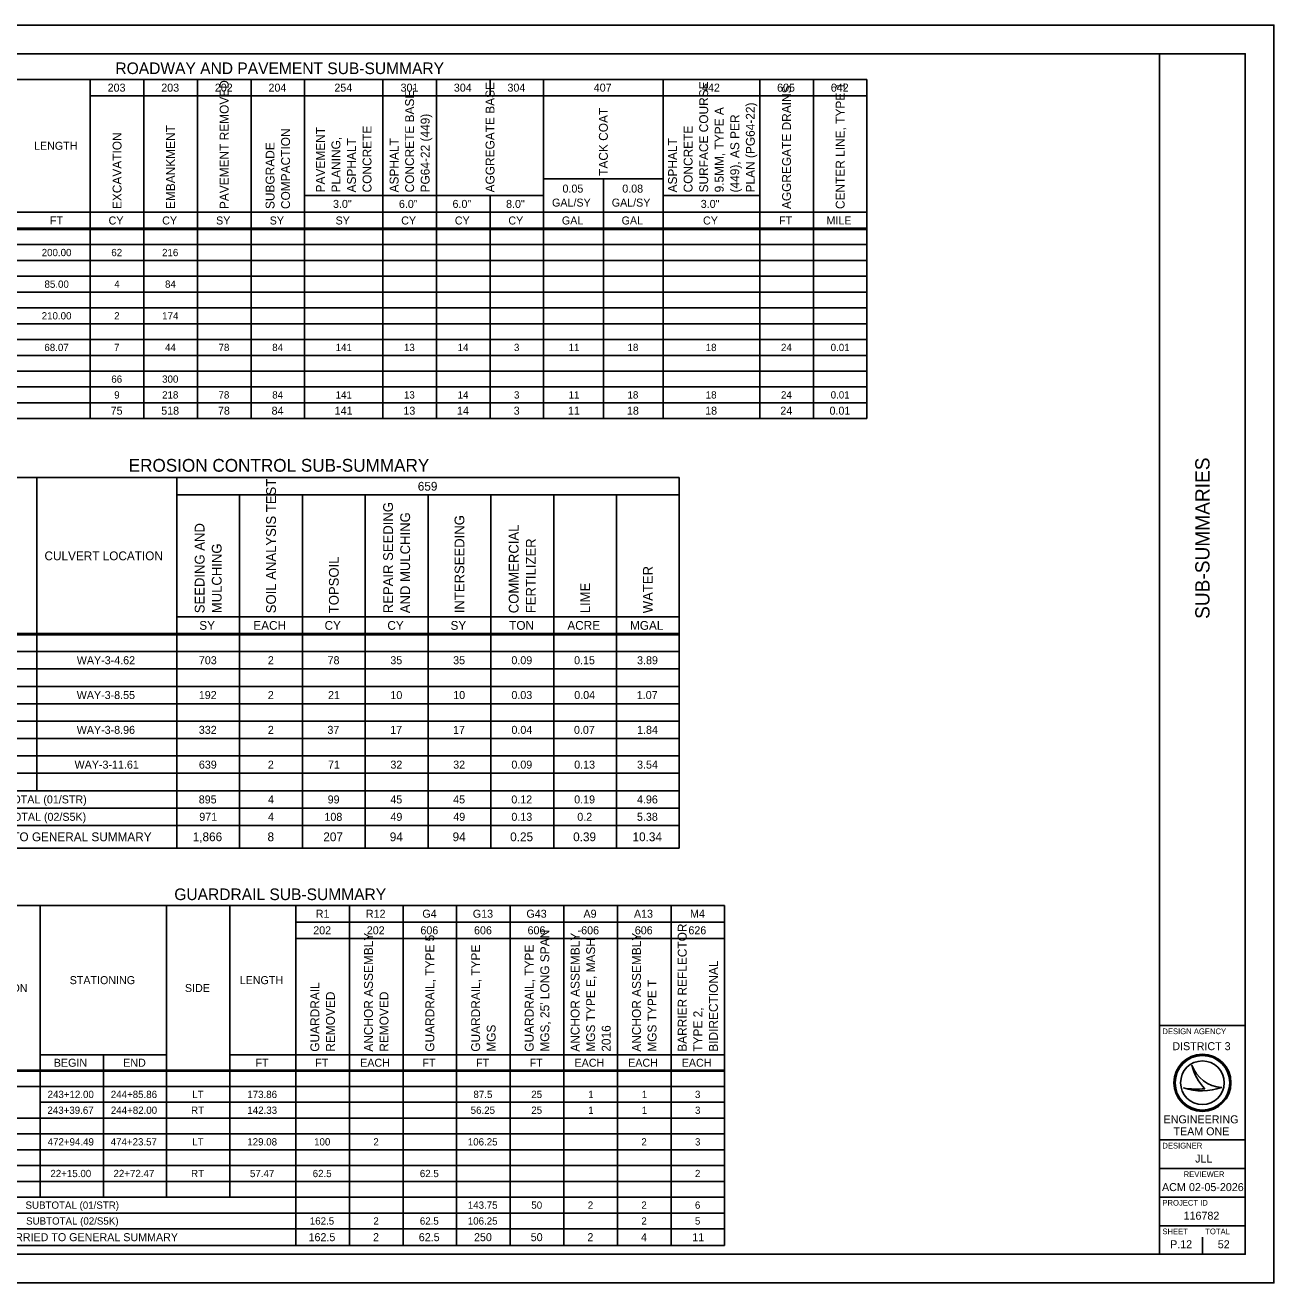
# Model space of a CAD drawing. Extents: x 0 to 34, y 0 to 22.
# Drawn here: x 12.15 to 34, y 0 to 22 of the extents above; entities that cross this region are included whole.
import ezdxf

# ---------------------------------------------------------------- set-up
doc = ezdxf.new("R2010")
doc.units = 0
for name, color, linetype in [('SH_Border', 7, 'Continuous'), ('SH_Cut_Line', 7, 'Continuous'), ('SH_Data', 7, 'Continuous'), ('SH_Text', 7, 'Continuous')]:
    doc.layers.add(name, color=color, linetype=linetype)

msp = doc.modelspace()

# ---------------------------------------------------------------- linework, layer by layer
at = {"layer": 'SH_Border'}
for p, q in [((32, 0.5), (32, 21.5)), ((32, 4.5), (33.5, 4.5)), ((32, 2.5), (33.5, 2.5)), ((32, 2), (33.5, 2)), ((32, 1.5), (33.5, 1.5)), ((32, 1), (33.5, 1))]:
    msp.add_line(p, q, dxfattribs=at)
msp.add_lwpolyline([(1.5, 21.5), (33.5, 21.5), (33.5, 0.5), (1.5, 0.5)], close=True, dxfattribs=at)
at = {"layer": 'SH_Cut_Line'}
msp.add_lwpolyline([(0, 0), (34, 0), (34, 22), (0, 22)], close=True, dxfattribs=at)
at = {"layer": 'SH_Data'}
for p, q in [((32.567, 3.81), (32.567, 3.81)), ((32.417, 3.41), (32.417, 3.41)), ((32.75, 3.5), (32.75, 3.5)), ((33.087, 3.419), (33.087, 3.419)), ((32.375, 0.675), (32.375, 0.675)), ((32.75, 0.5), (32.75, 0.8))]:
    msp.add_line(p, q, dxfattribs=at)
for radius in [0.5, 0.477, 0.477, 0.382]:
    msp.add_circle((32.75, 3.5), radius, dxfattribs=at)
for centre, radius, start, end in [((33.116, 3.998), 0.58, 198.9257, 198.9319), ((33.347, 3.97), 0.796, 191.6379, 191.6421), ((33.116, 3.998), 0.58, 198.9319, 267.1657), ((33.347, 3.97), 0.796, 191.6421, 226.0947), ((32.739, 4.37), 1.013, 251.4576, 290.0832), ((32.648, 4.654), 1.266, 259.4964, 259.4995), ((32.739, 4.37), 1.013, 251.4527, 251.4576), ((32.648, 4.654), 1.266, 259.4995, 276.6672)]:
    msp.add_arc(centre, radius, start, end, dxfattribs=at)
at = {"layer": 'SH_Text'}
for p, q in [((6.619, 21.052), (26.881, 21.052)), ((13.291, 21.052), (13.291, 18.447)), ((14.229, 21.052), (14.229, 18.447)), ((15.167, 21.052), (15.167, 18.447)), ((16.104, 21.052), (16.104, 18.447)), ((17.042, 21.052), (17.042, 18.447)), ((18.41, 21.052), (18.41, 18.447)), ((19.348, 21.052), (19.348, 18.447)), ((20.286, 21.052), (20.286, 20.762)), ((21.224, 21.052), (21.224, 18.447)), ((23.314, 21.052), (23.314, 18.447)), ((25.005, 21.052), (25.005, 18.447)), ((25.943, 21.052), (25.943, 18.447)), ((26.881, 21.052), (26.881, 18.428)), ((13.291, 20.762), (26.881, 20.762)), ((21.224, 19.309), (23.314, 19.309)), ((22.269, 19.309), (22.269, 18.447)), ((17.042, 19.019), (21.224, 19.019)), ((20.286, 19.019), (20.286, 18.447)), ((23.314, 19.019), (25.005, 19.019)), ((9.924, 18.728), (26.881, 18.728)), ((6.619, 18.447), (26.881, 18.447)), ((6.619, 18.428), (26.881, 18.428)), ((13.291, 18.428), (13.291, 15.117)), ((14.229, 18.428), (14.229, 15.117)), ((15.167, 18.428), (15.167, 15.117)), ((16.104, 18.428), (16.104, 15.117)), ((17.042, 18.428), (17.042, 15.117)), ((18.41, 18.428), (18.41, 15.117)), ((19.348, 18.428), (19.348, 15.117)), ((20.286, 18.428), (20.286, 15.117)), ((21.224, 18.428), (21.224, 15.117)), ((22.269, 18.428), (22.269, 15.117)), ((23.314, 18.428), (23.314, 15.117)), ((25.005, 18.428), (25.005, 15.117)), ((25.943, 18.428), (25.943, 15.117)), ((26.881, 18.447), (26.881, 15.117)), ((6.619, 18.161), (26.881, 18.161)), ((6.619, 17.884), (26.881, 17.884)), ((6.619, 17.607), (26.881, 17.607)), ((6.619, 17.331), (26.881, 17.331)), ((6.619, 17.054), (26.881, 17.054)), ((6.619, 16.777), (26.881, 16.777)), ((6.619, 16.501), (26.881, 16.501)), ((6.619, 16.224), (26.881, 16.224)), ((6.619, 15.947), (26.881, 15.947)), ((6.619, 15.671), (26.881, 15.671)), ((6.619, 15.394), (26.881, 15.394)), ((6.619, 15.117), (26.881, 15.117)), ((9.902, 14.087), (23.598, 14.087)), ((12.354, 14.087), (12.354, 11.358)), ((14.806, 14.087), (14.806, 11.358)), ((23.598, 14.087), (23.598, 11.337)), ((14.806, 13.782), (23.598, 13.782)), ((15.905, 13.782), (15.905, 11.358)), ((17.004, 13.782), (17.004, 11.358)), ((18.103, 13.782), (18.103, 11.358)), ((19.202, 13.782), (19.202, 11.358)), ((20.301, 13.782), (20.301, 11.358)), ((21.4, 13.782), (21.4, 11.358)), ((22.499, 13.782), (22.499, 11.358)), ((14.806, 11.652), (23.598, 11.652)), ((9.902, 11.358), (23.598, 11.358)), ((9.902, 11.337), (23.598, 11.337)), ((12.354, 11.337), (12.354, 8.608)), ((14.806, 11.337), (14.806, 7.604)), ((15.905, 11.337), (15.905, 7.604)), ((17.004, 11.337), (17.004, 7.604)), ((18.103, 11.337), (18.103, 7.604)), ((19.202, 11.337), (19.202, 7.604)), ((20.301, 11.337), (20.301, 7.604)), ((21.4, 11.337), (21.4, 7.604)), ((22.499, 11.337), (22.499, 7.604)), ((23.598, 11.358), (23.598, 7.604)), ((9.902, 11.043), (23.598, 11.043)), ((9.902, 10.739), (23.598, 10.739)), ((9.902, 10.434), (23.598, 10.434)), ((9.902, 10.13), (23.598, 10.13)), ((9.902, 9.826), (23.598, 9.826)), ((9.902, 9.521), (23.598, 9.521)), ((9.902, 9.217), (23.598, 9.217)), ((9.902, 8.913), (23.598, 8.913)), ((9.902, 8.608), (23.598, 8.608)), ((9.902, 8.304), (23.598, 8.304)), ((9.902, 8), (23.598, 8)), ((9.902, 7.604), (23.598, 7.604)), ((9.109, 6.603), (24.391, 6.603)), ((12.415, 6.603), (12.415, 3.721)), ((14.628, 6.603), (14.628, 3.721)), ((15.735, 6.603), (15.735, 3.721)), ((16.888, 6.603), (16.888, 3.721)), ((17.826, 6.603), (17.826, 3.721)), ((18.764, 6.603), (18.764, 3.721)), ((19.702, 6.603), (19.702, 3.721)), ((20.639, 6.603), (20.639, 3.721)), ((21.577, 6.603), (21.577, 3.721)), ((22.515, 6.603), (22.515, 3.721)), ((23.453, 6.603), (23.453, 3.721)), ((24.391, 6.603), (24.391, 3.702)), ((16.888, 6.312), (24.391, 6.312)), ((16.888, 6.022), (24.391, 6.022)), ((12.415, 3.988), (14.628, 3.988)), ((13.522, 3.988), (13.522, 3.721)), ((15.735, 3.988), (24.391, 3.988)), ((9.109, 3.721), (24.391, 3.721)), ((9.109, 3.702), (24.391, 3.702)), ((12.415, 3.702), (12.415, 1.498)), ((13.522, 3.702), (13.522, 1.498)), ((14.628, 3.702), (14.628, 1.498)), ((15.735, 3.702), (15.735, 1.498)), ((16.888, 3.702), (16.888, 0.654)), ((17.826, 3.702), (17.826, 0.654)), ((18.764, 3.702), (18.764, 0.654)), ((19.702, 3.702), (19.702, 0.654)), ((20.639, 3.702), (20.639, 0.654)), ((21.577, 3.702), (21.577, 0.654)), ((22.515, 3.702), (22.515, 0.654)), ((23.453, 3.702), (23.453, 0.654)), ((24.391, 3.721), (24.391, 0.654)), ((9.109, 3.435), (24.391, 3.435)), ((12.415, 3.158), (24.391, 3.158)), ((9.109, 2.881), (24.391, 2.881)), ((9.109, 2.605), (24.391, 2.605)), ((9.109, 2.328), (24.391, 2.328)), ((9.109, 2.051), (24.391, 2.051)), ((9.109, 1.775), (24.391, 1.775)), ((9.109, 1.498), (24.391, 1.498)), ((9.109, 1.221), (24.391, 1.221)), ((9.109, 0.945), (24.391, 0.945)), ((9.109, 0.654), (24.391, 0.654))]:
    msp.add_line(p, q, dxfattribs=at)

# ---------------------------------------------------------------- texts
at = {"layer": 'SH_Data'}
msp.add_text('SUB-SUMMARIES', height=0.25, rotation=90, dxfattribs=at).set_placement((32.875, 11.614))
for s, height, p in [('DESIGN AGENCY', 0.1, (32.05, 4.35)), ('DISTRICT 3', 0.14, (32.224, 4.07)), ('ENGINEERING', 0.14, (32.071, 2.79)), ('TEAM ONE', 0.14, (32.244, 2.58)), ('DESIGNER', 0.1, (32.05, 2.35)), ('JLL', 0.14, (32.623, 2.105)), ('REVIEWER', 0.1, (32.422, 1.85)), ('ACM', 0.14, (32.043, 1.605)), ('02-05-2026', 0.14, (32.515, 1.605)), ('PROJECT ID', 0.1, (32.05, 1.35)), ('116782', 0.14, (32.421, 1.105)), ('SHEET', 0.1, (32.05, 0.85)), ('TOTAL', 0.1, (32.8, 0.85)), ('P.12', 0.14, (32.185, 0.605)), ('52', 0.14, (33.019, 0.605))]:
    msp.add_text(s, height=height, dxfattribs=at).set_placement(p)
at = {"layer": 'SH_Text'}
for s, height, p in [('ROADWAY AND PAVEMENT SUB-SUMMARY', 0.20364, (13.732, 21.144)), ('203', 0.14, (13.596, 20.837)), ('203', 0.14, (14.534, 20.837)), ('202', 0.14, (15.471, 20.837)), ('204', 0.14, (16.41, 20.837)), ('254', 0.14, (17.563, 20.837)), ('301', 0.14, (18.721, 20.837)), ('304', 0.14, (19.653, 20.837)), ('304', 0.14, (20.591, 20.837)), ('407', 0.14, (22.101, 20.837)), ('442', 0.14, (23.995, 20.837)), ('605', 0.14, (25.309, 20.837)), ('642', 0.14, (26.248, 20.837)), ('LENGTH', 0.14, (12.308, 19.82)), ('0.05 ', 0.14, (21.554, 19.071)), ('0.08 ', 0.14, (22.6, 19.071)), ('3.0"', 0.14, (17.539, 18.803)), ('6.0"', 0.14, (18.692, 18.803)), ('6.0"', 0.14, (19.63, 18.803)), ('8.0"', 0.14, (20.567, 18.803)), ('GAL/SY', 0.14, (21.371, 18.826)), ('GAL/SY', 0.14, (22.416, 18.826)), ('3.0"', 0.14, (23.973, 18.803)), ('FT', 0.14, (12.585, 18.513)), ('CY', 0.14, (13.612, 18.513)), ('CY', 0.14, (14.55, 18.513)), ('SY', 0.14, (15.493, 18.513)), ('SY', 0.14, (16.431, 18.513)), ('SY', 0.14, (17.584, 18.513)), ('CY', 0.14, (18.732, 18.513)), ('CY', 0.14, (19.67, 18.513)), ('CY', 0.14, (20.607, 18.513)), ('GAL', 0.14, (21.543, 18.513)), ('GAL', 0.14, (22.588, 18.513)), ('CY', 0.14, (24.013, 18.513)), ('FT', 0.14, (25.345, 18.513)), ('MILE', 0.14, (26.173, 18.513)), ('200.00', 0.1273, (12.442, 17.959)), ('62', 0.1273, (13.66, 17.959)), ('216', 0.1273, (14.548, 17.959)), ('85.00', 0.1273, (12.491, 17.406)), ('4', 0.127, (13.712, 17.406)), ('84', 0.1273, (14.6, 17.406)), ('210.00', 0.1273, (12.442, 16.852)), ('2', 0.127, (13.71, 16.852)), ('174', 0.1273, (14.55, 16.852)), ('68.07', 0.1273, (12.489, 16.299)), ('7', 0.127, (13.707, 16.299)), ('44', 0.1273, (14.6, 16.299)), ('78', 0.1273, (15.536, 16.299)), ('84', 0.1273, (16.475, 16.299)), ('141', 0.1273, (17.585, 16.299)), ('13', 0.1273, (18.78, 16.299)), ('14', 0.1273, (19.719, 16.299)), ('3', 0.127, (20.705, 16.299)), ('11', 0.1273, (21.661, 16.299)), ('18', 0.1273, (22.692, 16.299)), ('18', 0.1273, (24.06, 16.299)), ('24', 0.1273, (25.377, 16.299)), ('0.01', 0.1273, (26.246, 16.299)), ('66', 0.1273, (13.66, 15.745)), ('300', 0.1273, (14.549, 15.745)), ('9', 0.127, (13.711, 15.469)), ('218', 0.1273, (14.549, 15.469)), ('78', 0.1273, (15.536, 15.469)), ('84', 0.1273, (16.475, 15.469)), ('141', 0.1273, (17.585, 15.469)), ('13', 0.1273, (18.78, 15.469)), ('14', 0.1273, (19.719, 15.469)), ('3', 0.127, (20.705, 15.469)), ('11', 0.1273, (21.661, 15.469)), ('18', 0.1273, (22.692, 15.469)), ('18', 0.1273, (24.06, 15.469)), ('24', 0.1273, (25.377, 15.469)), ('0.01', 0.1273, (26.246, 15.469)), ('75', 0.14, (13.649, 15.186)), ('518', 0.14, (14.533, 15.186)), ('78', 0.14, (15.526, 15.186)), ('84', 0.14, (16.464, 15.186)), ('141', 0.14, (17.568, 15.186)), ('13', 0.14, (18.77, 15.186)), ('14', 0.14, (19.708, 15.186)), ('3', 0.14, (20.7, 15.186)), ('11', 0.14, (21.649, 15.186)), ('18', 0.14, (22.682, 15.186)), ('18', 0.14, (24.05, 15.186)), ('24', 0.14, (25.365, 15.186)), ('0.01', 0.14, (26.226, 15.186)), ('EROSION CONTROL SUB-SUMMARY', 0.224, (13.964, 14.188)), ('659', 0.154, (19.022, 13.857)), ('CULVERT LOCATION', 0.154, (12.491, 12.64)), ('SY', 0.154, (15.199, 11.423)), ('EACH', 0.154, (16.145, 11.423)), ('CY', 0.154, (17.391, 11.423)), ('CY', 0.154, (18.49, 11.423)), ('SY', 0.154, (19.595, 11.423)), ('TON', 0.154, (20.621, 11.423)), ('ACRE', 0.154, (21.639, 11.423)), ('MGAL', 0.154, (22.735, 11.423)), ('WAY-3-4.62', 0.14, (13.056, 10.821)), ('703', 0.14, (15.192, 10.821)), ('2', 0.14, (16.399, 10.821)), ('78', 0.14, (17.444, 10.821)), ('35', 0.14, (18.542, 10.821)), ('35', 0.14, (19.641, 10.821)), ('0.09', 0.14, (20.66, 10.821)), ('0.15', 0.14, (21.757, 10.821)), ('3.89', 0.14, (22.859, 10.821)), ('WAY-3-8.55', 0.14, (13.055, 10.212)), ('192', 0.14, (15.191, 10.212)), ('2', 0.14, (16.399, 10.212)), ('21', 0.14, (17.452, 10.212)), ('10', 0.14, (18.543, 10.212)), ('10', 0.14, (19.642, 10.212)), ('0.03', 0.14, (20.66, 10.212)), ('0.04', 0.14, (21.76, 10.212)), ('1.07', 0.14, (22.854, 10.212)), ('WAY-3-8.96', 0.14, (13.055, 9.603)), ('332', 0.14, (15.191, 9.603)), ('2', 0.14, (16.399, 9.603)), ('37', 0.14, (17.441, 9.603)), ('17', 0.14, (18.54, 9.603)), ('17', 0.14, (19.639, 9.603)), ('0.04', 0.14, (20.661, 9.603)), ('0.07', 0.14, (21.755, 9.603)), ('1.84', 0.14, (22.859, 9.603)), ('WAY-3-11.61', 0.14, (13.017, 8.995)), ('639', 0.14, (15.192, 8.995)), ('2', 0.14, (16.399, 8.995)), ('71', 0.14, (17.452, 8.995)), ('32', 0.14, (18.543, 8.995)), ('32', 0.14, (19.642, 8.995)), ('0.09', 0.14, (20.66, 8.995)), ('0.13', 0.14, (21.759, 8.995)), ('3.54', 0.14, (22.859, 8.995)), ('SUBTOTAL (01/STR)', 0.14, (11.43, 8.386)), ('895', 0.14, (15.19, 8.386)), ('4', 0.14, (16.401, 8.386)), ('99', 0.14, (17.445, 8.386)), ('45', 0.14, (18.542, 8.386)), ('45', 0.14, (19.641, 8.386)), ('0.12', 0.14, (20.659, 8.386)), ('0.19', 0.14, (21.759, 8.386)), ('4.96', 0.14, (22.857, 8.386)), ('SUBTOTAL (02/S5K)', 0.14, (11.441, 8.082)), ('971', 0.14, (15.199, 8.082)), ('4', 0.14, (16.401, 8.082)), ('108', 0.14, (17.389, 8.082)), ('49', 0.14, (18.544, 8.082)), ('49', 0.14, (19.643, 8.082)), ('0.13', 0.14, (20.66, 8.082)), ('0.2', 0.14, (21.813, 8.082)), ('5.38', 0.14, (22.857, 8.082)), ('TOTALS CARRIED TO GENERAL SUMMARY', 0.154, (10.085, 7.725)), ('1,866', 0.154, (15.084, 7.725)), ('8', 0.154, (16.393, 7.725)), ('207', 0.154, (17.369, 7.725)), ('94', 0.154, (18.532, 7.725)), ('94', 0.154, (19.631, 7.725)), ('0.25', 0.154, (20.639, 7.725)), ('0.39', 0.154, (21.74, 7.725)), ('10.34', 0.154, (22.779, 7.725)), ('GUARDRAIL SUB-SUMMARY', 0.20364, (14.762, 6.695)), ('R1', 0.14, (17.237, 6.387)), ('R12', 0.14, (18.114, 6.387)), ('G4', 0.14, (19.102, 6.387)), ('G13', 0.14, (19.985, 6.387)), ('G43', 0.14, (20.923, 6.387)), ('A9', 0.14, (21.921, 6.387)), ('A13', 0.14, (22.804, 6.387)), ('M4', 0.14, (23.785, 6.387)), ('202', 0.14, (17.193, 6.097)), ('202', 0.14, (18.13, 6.097)), ('606', 0.14, (19.068, 6.097)), ('606', 0.14, (20.006, 6.097)), ('606', 0.14, (20.943, 6.097)), ('606', 0.14, (21.881, 6.097)), ('606', 0.14, (22.819, 6.097)), ('626', 0.14, (23.757, 6.097)), ('STATIONING', 0.14, (12.932, 5.225)), ('LENGTH', 0.14, (15.906, 5.225)), ('CULVERT LOCATION', 0.14, (10.311, 5.087)), ('SIDE', 0.14, (14.948, 5.087)), ('BEGIN', 0.14, (12.654, 3.78)), ('END', 0.14, (13.868, 3.78)), ('FT', 0.14, (16.183, 3.78)), ('FT', 0.14, (17.228, 3.78)), ('EACH', 0.14, (18.014, 3.78)), ('FT', 0.14, (19.104, 3.78)), ('FT', 0.14, (20.041, 3.78)), ('FT', 0.14, (20.979, 3.78)), ('EACH', 0.14, (21.765, 3.78)), ('EACH', 0.14, (22.703, 3.78)), ('EACH', 0.14, (23.64, 3.78)), ('243+12.00', 0.1273, (12.545, 3.233)), ('244+85.86', 0.1273, (13.651, 3.233)), ('LT', 0.1273, (15.076, 3.233)), ('173.86', 0.1273, (16.039, 3.233)), ('87.5', 0.1273, (19.996, 3.233)), ('25', 0.1273, (21.008, 3.233)), ('1', 0.127, (22.004, 3.233)), ('1', 0.127, (22.941, 3.233)), ('3', 0.127, (23.872, 3.233)), ('243+39.67', 0.1273, (12.542, 2.956)), ('244+82.00', 0.1273, (13.652, 2.956)), ('RT', 0.1273, (15.056, 2.956)), ('142.33', 0.1273, (16.04, 2.956)), ('56.25', 0.1273, (19.947, 2.956)), ('25', 0.1273, (21.008, 2.956)), ('1', 0.127, (22.004, 2.956)), ('1', 0.127, (22.941, 2.956)), ('3', 0.127, (23.872, 2.956)), ('472+94.49', 0.1273, (12.546, 2.403)), ('474+23.57', 0.1273, (13.649, 2.403)), ('LT', 0.1273, (15.076, 2.403)), ('129.08', 0.1273, (16.039, 2.403)), ('100', 0.1273, (17.208, 2.403)), ('2', 0.127, (18.245, 2.403)), ('106.25', 0.1273, (19.897, 2.403)), ('2', 0.127, (22.934, 2.403)), ('3', 0.127, (23.872, 2.403)), ('22+15.00', 0.1273, (12.594, 1.849)), ('22+72.47', 0.1273, (13.698, 1.849)), ('RT', 0.1273, (15.056, 1.849)), ('57.47', 0.1273, (16.086, 1.849)), ('62.5', 0.1273, (17.183, 1.849)), ('62.5', 0.1273, (19.058, 1.849)), ('2', 0.127, (23.872, 1.849)), ('SUBTOTAL (01/STR)', 0.12727, (12.159, 1.296)), ('143.75', 0.1273, (19.897, 1.296)), ('50', 0.1273, (21.009, 1.296)), ('2', 0.127, (21.996, 1.296)), ('2', 0.127, (22.934, 1.296)), ('6', 0.127, (23.871, 1.296)), ('SUBTOTAL (02/S5K)', 0.12727, (12.169, 1.019)), ('162.5', 0.1273, (17.133, 1.019)), ('2', 0.127, (18.245, 1.019)), ('62.5', 0.1273, (19.058, 1.019)), ('106.25', 0.1273, (19.897, 1.019)), ('2', 0.127, (22.934, 1.019)), ('5', 0.127, (23.871, 1.019)), ('TOTALS CARRIED TO GENERAL SUMMARY', 0.14, (10.936, 0.729)), ('162.5', 0.14, (17.111, 0.729)), ('2', 0.14, (18.239, 0.729)), ('62.5', 0.14, (19.04, 0.729)), ('250', 0.14, (20.006, 0.729)), ('50', 0.14, (20.998, 0.729)), ('2', 0.14, (21.99, 0.729)), ('4', 0.14, (22.929, 0.729)), ('11', 0.14, (23.825, 0.729))]:
    msp.add_text(s, height=height, dxfattribs=at).set_placement(p)
for s, height, p in [('PAVEMENT REMOVED', 0.15558, (15.713, 18.783)), ('AGGREGATE BASE', 0.15558, (20.364, 19.074)), ('SURFACE COURSE, ', 0.15558, (24.102, 19.074)), ('AGGREGATE DRAINS', 0.15558, (25.552, 18.783)), ('CENTER LINE, TYPE 1', 0.15558, (26.49, 18.783)), ('CONCRETE BASE, ', 0.15558, (18.957, 19.074)), ('TACK COAT', 0.1556, (22.347, 19.364)), ('9.5MM, TYPE A ', 0.15558, (24.374, 19.074)), ('PLAN (PG64-22)', 0.15558, (24.918, 19.074)), ('EMBANKMENT', 0.1556, (14.775, 18.783)), ('PG64-22 (449)', 0.15558, (19.229, 19.074)), ('(449), AS PER ', 0.15558, (24.646, 19.074)), ('EXCAVATION', 0.1556, (13.838, 18.783)), ('COMPACTION', 0.1556, (16.787, 18.783)), ('PAVEMENT ', 0.1556, (17.396, 19.074)), ('PLANING, ', 0.1556, (17.668, 19.074)), ('CONCRETE', 0.1556, (18.212, 19.074)), ('CONCRETE ', 0.1556, (23.829, 19.074)), ('SUBGRADE ', 0.1556, (16.515, 18.783)), ('ASPHALT ', 0.1556, (17.94, 19.074)), ('ASPHALT ', 0.1556, (18.685, 19.074)), ('ASPHALT ', 0.1556, (23.557, 19.074)), ('SOIL ANALYSIS TEST', 0.17111, (16.54, 11.713)), ('REPAIR SEEDING ', 0.17111, (18.588, 11.713)), ('AND MULCHING', 0.17111, (18.887, 11.713)), ('SEEDING AND ', 0.17111, (15.291, 11.713)), ('INTERSEEDING', 0.17111, (19.837, 11.713)), ('COMMERCIAL ', 0.17111, (20.786, 11.713)), ('FERTILIZER', 0.1711, (21.086, 11.713)), ('MULCHING', 0.1711, (15.59, 11.713)), ('TOPSOIL', 0.1711, (17.639, 11.713)), ('WATER', 0.1711, (23.134, 11.713)), ('LIME', 0.1711, (22.035, 11.713)), ('ANCHOR ASSEMBLY, ', 0.15558, (21.852, 4.043)), ('ANCHOR ASSEMBLY, ', 0.15558, (22.926, 4.043)), ('BARRIER REFLECTOR, ', 0.15558, (23.727, 4.043)), ('ANCHOR ASSEMBLY ', 0.15558, (18.237, 4.043)), ('GUARDRAIL, TYPE 5', 0.15558, (19.311, 4.043)), ("MGS, 25' LONG SPAN", 0.15558, (21.322, 4.043)), ('MGS TYPE E, MASH ', 0.15558, (22.124, 4.043)), ('GUARDRAIL, TYPE ', 0.15558, (20.112, 4.043)), ('GUARDRAIL, TYPE ', 0.15558, (21.05, 4.043)), ('BIDIRECTIONAL', 0.15558, (24.272, 4.043)), ('MGS TYPE T', 0.1556, (23.198, 4.043)), ('GUARDRAIL ', 0.1556, (17.299, 4.043)), ('REMOVED', 0.1556, (17.571, 4.043)), ('REMOVED', 0.1556, (18.509, 4.043)), ('TYPE 2, ', 0.1556, (23.999, 4.043)), ('MGS', 0.1556, (20.384, 4.043)), ('2016', 0.1556, (22.396, 4.043))]:
    msp.add_text(s, height=height, rotation=90, dxfattribs=at).set_placement(p)

doc.saveas('drawing.dxf')
